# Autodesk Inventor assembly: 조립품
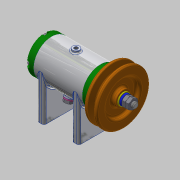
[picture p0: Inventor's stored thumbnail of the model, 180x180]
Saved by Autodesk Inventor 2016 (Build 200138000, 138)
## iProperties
Created: 2020-07
Part Number: 조립품
Material: 일반
Document SubType Name: Assembly
Designer: 605-11
Author: 605-11
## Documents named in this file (15)
- C:\Users\605-11\Desktop\700706V1011\조립품.iam
- C:\Users\605-11\Desktop\700706V1011\본체.ipt
- C:\Users\605-11\Desktop\700706V1011\뒤커버.ipt
- C:\Users\605-11\Desktop\700706V1011\앞커버.ipt
- C:\Users\605-11\Desktop\700706V1011\베어링 6002.ipt
- C:\Users\605-11\Desktop\700706V1011\볼트 M4x12.ipt
- C:\Users\605-11\Desktop\700706V1011\오일 실 15 25 7.ipt
- C:\Users\605-11\Desktop\700706V1011\축.ipt
- C:\Users\605-11\Desktop\700706V1011\키 3x3x12.ipt
- C:\Users\605-11\Desktop\700706V1011\V벨트풀리.ipt
- C:\Users\605-11\Desktop\700706V1011\와셔 8x17.ipt
- C:\Users\605-11\Desktop\700706V1011\스프링와셔 8.ipt
- C:\Users\605-11\Desktop\700706V1011\너트 M8.ipt
- C:\Users\605-11\Desktop\700706V1011\와셔 6x11.5.ipt
- C:\Users\605-11\Desktop\700706V1011\볼트 M6x8.ipt
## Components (1 placed, 1 different names)
1. V벨트풀리:1
